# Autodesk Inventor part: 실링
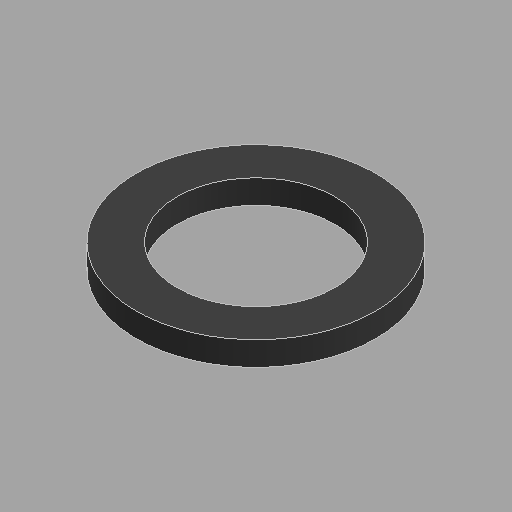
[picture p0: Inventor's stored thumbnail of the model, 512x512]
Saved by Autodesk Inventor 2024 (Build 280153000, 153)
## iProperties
Created: 2025-02
Part Number: 실링
Material: 고무
Document SubType Name: Modeling
Designer: kh_501
Density: 0.93 g/cm^3
Appearance: 기본값
Author: jhkim
Sending System: Autodesk Inventor 2025
Preprocessor: ST-DEVELOPER v20
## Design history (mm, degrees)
feature "솔리드1"
node "솔리드2"
